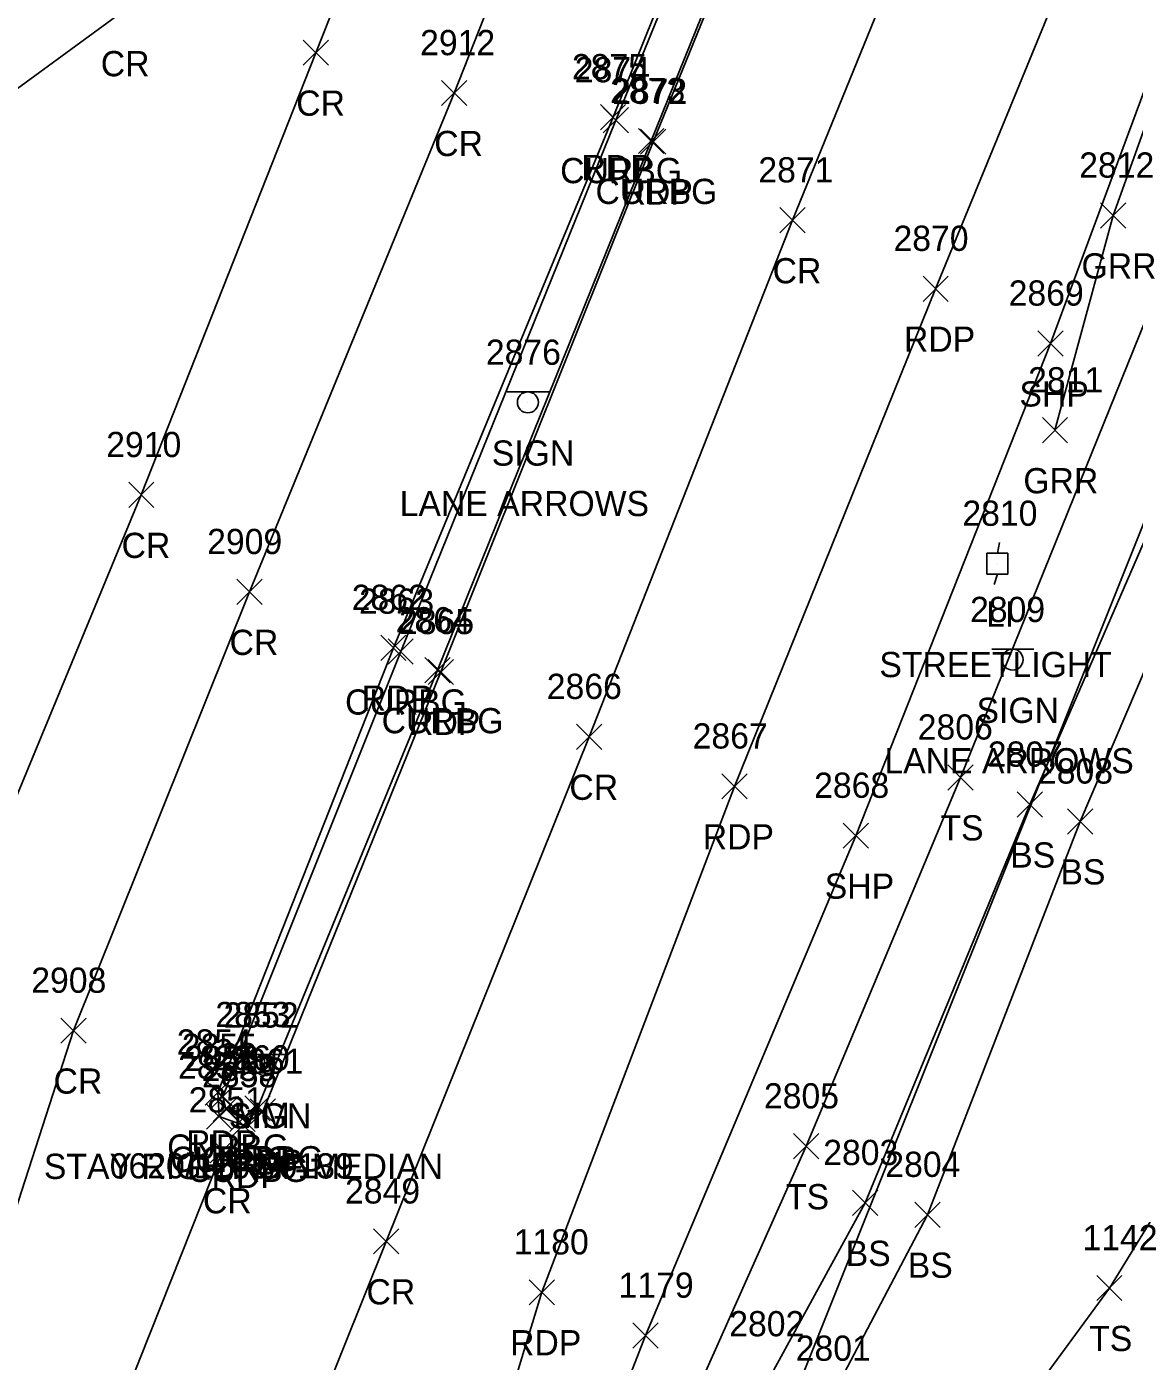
# Model space of a CAD drawing. Extents: x 1623612 to 1625808, y 621345 to 627748.
# Drawn here: x 1624751.6 to 1624839.4, y 626381.4 to 626487.2 of the extents above; entities that cross this region are included whole.
import ezdxf

# ---------------------------------------------------------------- set-up
doc = ezdxf.new("R2010")
doc.units = 0
for name, color, linetype in [('DCP', 7, 'Continuous'), ('L_A', 7, 'Continuous'), ('L_I', 7, 'Continuous'), ('L_TIC', 7, 'Continuous'), ('LELB', 7, 'Continuous'), ('P_A', 7, 'Continuous'), ('P_I', 7, 'Continuous'), ('P_TIC', 7, 'Continuous'), ('PET', 7, 'Continuous'), ('PRC', 7, 'Continuous'), ('PSP', 7, 'Continuous'), ('R_A', 7, 'Continuous'), ('R_I', 7, 'Continuous'), ('R_TIC', 7, 'Continuous'), ('RC', 7, 'Continuous'), ('RGR', 7, 'Continuous'), ('S_A', 7, 'Continuous'), ('S_C', 7, 'Continuous'), ('S_I', 7, 'Continuous'), ('SRM', 7, 'Continuous'), ('SSGN', 7, 'Continuous'), ('U_A', 7, 'Continuous'), ('U_C', 7, 'Continuous'), ('U_I', 7, 'Continuous'), ('ULP', 7, 'Continuous')]:
    doc.layers.add(name, color=color, linetype=linetype)

msp = doc.modelspace()

# ---------------------------------------------------------------- linework, layer by layer
at = {"layer": 'DCP'}
msp.add_lwpolyline([(1624809.95, 626372.49), (1624894.12, 626582.82)], dxfattribs=at)
at = {"layer": 'L_TIC'}
for points in [[(1624824.59, 626426.7), (1624826.59, 626428.7)], [(1624826.59, 626426.7), (1624824.59, 626428.7)], [(1624830.09, 626424.55), (1624832.09, 626426.55)], [(1624832.09, 626424.55), (1624830.09, 626426.55)], [(1624834.07, 626423.21), (1624836.07, 626425.21)], [(1624836.07, 626423.21), (1624834.07, 626425.21)], [(1624812.35, 626397.45), (1624814.35, 626399.45)], [(1624814.35, 626397.45), (1624812.35, 626399.45)], [(1624817.04, 626392.96), (1624819.04, 626394.96)], [(1624819.04, 626392.96), (1624817.04, 626394.96)], [(1624821.97, 626392.02), (1624823.97, 626394.02)], [(1624823.97, 626392.02), (1624821.97, 626394.02)], [(1624836.39, 626386.21), (1624838.39, 626388.21)], [(1624838.39, 626386.21), (1624836.39, 626388.21)]]:
    msp.add_lwpolyline(points, dxfattribs=at)
at = {"layer": 'LELB'}
for points in [[(1624803, 626375.22), (1624813.35, 626398.45), (1624825.59, 626427.7), (1624842.6, 626469.77), (1624853.82, 626508.25), (1624866.96, 626541.11), (1624879.6, 626570.92), (1624891.67, 626600.55), (1624909.69, 626627.37), (1624926.15, 626668.66), (1624945.08, 626696.18), (1624959.4, 626716.07), (1624979.06, 626741.61), (1624996.92, 626763.33), (1625023.93, 626790.77), (1625051.04, 626817.18), (1625076.24, 626838.55), (1625119.15, 626870.61), (1625147.29, 626888.18), (1625173.2, 626903.38), (1625206.27, 626920.6), (1625246.39, 626940.92)], [(1624810.6, 626380.38), (1624818.04, 626393.96), (1624831.09, 626425.55), (1624850.8, 626470.91), (1624859.76, 626506.71), (1624871.37, 626535.84), (1624886.95, 626567.84), (1624894.07, 626585.15), (1624895.49, 626590.47), (1624915.6, 626622.48), (1624934.63, 626664.39), (1624951.07, 626691.63), (1624965.13, 626713.06), (1624983.66, 626737.48), (1625004.4, 626758.94), (1625029.36, 626786.77), (1625054.16, 626807.16), (1625052.62, 626815.07), (1625083.54, 626836.73), (1625122.13, 626865.73), (1625150.08, 626884.49), (1625175.36, 626899.84), (1625209.28, 626915.51), (1625248.24, 626935.95)], [(1624815.3, 626378.44), (1624822.97, 626393.02), (1624835.07, 626424.21), (1624854.93, 626470.78), (1624864.02, 626503.22), (1624876, 626534.5), (1624889.39, 626566.85), (1624897.36, 626584.29), (1624900.1, 626587.8), (1624917.68, 626620.81), (1624936.92, 626663.47), (1624953.32, 626690.33), (1624968.57, 626711.23), (1624977.21, 626720.96), (1624986.38, 626735.04), (1625009.06, 626756.63), (1625033.16, 626784.59), (1625055.85, 626805.24), (1625057.84, 626806.47), (1625088.69, 626829.26), (1625128.34, 626855.41), (1625156.9, 626876.93)], [(1624911.43, 626189.27), (1624902.06, 626212.81), (1624885.19, 626234.26), (1624858.97, 626273.95), (1624836.34, 626299.76), (1624822.3, 626315.86), (1624819.42, 626329.22), (1624818.84, 626346.9), (1624823.2, 626367.84), (1624837.39, 626387.21), (1624868.75, 626438.34), (1624881.95, 626485.16), (1624894.55, 626521.87)]]:
    msp.add_lwpolyline(points, dxfattribs=at)
at = {"layer": 'P_TIC'}
for points in [[(1624773.5, 626484.17), (1624775.5, 626486.17)], [(1624775.5, 626484.17), (1624773.5, 626486.17)], [(1624784.45, 626480.97), (1624786.45, 626482.97)], [(1624786.45, 626480.97), (1624784.45, 626482.97)], [(1624797.05, 626479.06), (1624799.05, 626481.06)], [(1624799.05, 626479.06), (1624797.05, 626481.06)], [(1624800.24, 626477.11), (1624802.24, 626479.11)], [(1624802.24, 626477.11), (1624800.24, 626479.11)], [(1624811.27, 626470.88), (1624813.27, 626472.88)], [(1624813.27, 626470.88), (1624811.27, 626472.88)], [(1624822.62, 626465.45), (1624824.62, 626467.45)], [(1624824.62, 626465.45), (1624822.62, 626467.45)], [(1624831.73, 626461.11), (1624833.73, 626463.11)], [(1624833.73, 626461.11), (1624831.73, 626463.11)], [(1624759.66, 626449.1), (1624761.66, 626451.1)], [(1624761.66, 626449.1), (1624759.66, 626451.1)], [(1624768.23, 626441.41), (1624770.23, 626443.41)], [(1624770.23, 626441.41), (1624768.23, 626443.41)], [(1624779.64, 626436.98), (1624781.64, 626438.98)], [(1624781.64, 626436.98), (1624779.64, 626438.98)], [(1624783.4, 626435.06), (1624785.4, 626437.06)], [(1624785.4, 626435.06), (1624783.4, 626437.06)], [(1624795.16, 626429.92), (1624797.16, 626431.92)], [(1624797.16, 626429.92), (1624795.16, 626431.92)], [(1624806.67, 626425.99), (1624808.67, 626427.99)], [(1624808.67, 626425.99), (1624806.67, 626427.99)], [(1624816.3, 626422.08), (1624818.3, 626424.08)], [(1624818.3, 626422.08), (1624816.3, 626424.08)], [(1624754.28, 626406.62), (1624756.28, 626408.62)], [(1624756.28, 626406.62), (1624754.28, 626408.62)], [(1624765.73, 626401.72), (1624767.73, 626403.72)], [(1624767.73, 626401.72), (1624765.73, 626403.72)], [(1624765.73, 626401.72), (1624767.73, 626403.72)], [(1624767.73, 626401.72), (1624765.73, 626403.72)], [(1624765.83, 626399.8), (1624767.83, 626401.8)], [(1624767.83, 626399.8), (1624765.83, 626401.8)], [(1624769.3, 626400.2), (1624771.3, 626402.2)], [(1624771.3, 626400.2), (1624769.3, 626402.2)], [(1624767.74, 626399.13), (1624769.74, 626401.13)], [(1624769.74, 626399.13), (1624767.74, 626401.13)], [(1624766.12, 626397.13), (1624768.12, 626399.13)], [(1624768.12, 626397.13), (1624766.12, 626399.13)], [(1624779.07, 626389.91), (1624781.07, 626391.91)], [(1624781.07, 626389.91), (1624779.07, 626391.91)], [(1624791.4, 626385.87), (1624793.4, 626387.87)], [(1624793.4, 626385.87), (1624791.4, 626387.87)], [(1624799.63, 626382.44), (1624801.63, 626384.44)], [(1624801.63, 626382.44), (1624799.63, 626384.44)]]:
    msp.add_lwpolyline(points, dxfattribs=at)
at = {"layer": 'PET'}
for points in [[(1624766.73, 626402.72), (1624780.64, 626437.98), (1624798.05, 626480.06), (1624815.81, 626524.2), (1624827.52, 626552.84), (1624846.03, 626598.35), (1624859.48, 626631.2), (1624866.7, 626649.12), (1624872.17, 626667.17), (1624878.33, 626693.72), (1624888.34, 626729.13), (1624901.95, 626767.65), (1624921.26, 626815.38), (1624932.49, 626843.12), (1624948.41, 626882.32), (1624965.05, 626923.7), (1624979.42, 626958.68), (1624996.36, 626998.74), (1625014.07, 627035.12), (1625037.87, 627077.32), (1625060.67, 627111.97), (1625086.82, 627148.78)], [(1624766.73, 626402.72), (1624766.83, 626400.8), (1624768.74, 626400.13), (1624770.3, 626401.2), (1624784.4, 626436.06), (1624801.24, 626478.11), (1624819.49, 626522.96), (1624830.85, 626551.33), (1624849.51, 626596.84), (1624862.82, 626629.63), (1624870.03, 626647.48), (1624887.2, 626689.75), (1624900.85, 626722.92), (1624916.26, 626761.13), (1624935.59, 626808.93), (1624946.63, 626835.79), (1624962.93, 626876.24), (1624979.58, 626917.12), (1624994.1, 626953.25), (1625010.3, 626991.9), (1625027.96, 627028.75), (1625048.74, 627069.01), (1625070.59, 627104.96), (1625095.62, 627141.4)], [(1624787.66, 626371.25), (1624792.4, 626386.87), (1624807.67, 626426.99), (1624823.62, 626466.45), (1624842.65, 626512.83), (1624858.28, 626551.42), (1624873.9, 626593.46)]]:
    msp.add_lwpolyline(points, dxfattribs=at)
at = {"layer": 'PRC'}
for points in [[(1624734.72, 626386.78), (1624744.9, 626412.05), (1624760.66, 626450.1), (1624774.5, 626485.17), (1624790.6, 626525.88), (1624807.67, 626567), (1624823.36, 626605.3), (1624843.35, 626654.29), (1624857.69, 626692.78)], [(1624746.25, 626379.72), (1624755.28, 626407.62), (1624769.23, 626442.41), (1624785.45, 626481.97), (1624800.21, 626519.37), (1624817.93, 626562.99), (1624833.55, 626600.88), (1624853.94, 626650.59), (1624866.71, 626682.78)], [(1624769.71, 626365.07), (1624780.07, 626390.91), (1624796.16, 626430.92), (1624812.27, 626471.88), (1624830.75, 626517.25), (1624847.51, 626558.11), (1624861.26, 626592.1)], [(1624657.54, 626467.38), (1624680.7, 626465.41), (1624702.49, 626466.85), (1624727.83, 626471.96), (1624748.65, 626480.73), (1624759.02, 626488.3)], [(1624754.79, 626367.08), (1624767.12, 626398.13)]]:
    msp.add_lwpolyline(points, dxfattribs=at)
at = {"layer": 'PSP'}
msp.add_lwpolyline([(1624794.65, 626368.04), (1624800.63, 626383.44), (1624817.3, 626423.08), (1624832.73, 626462.11), (1624850.47, 626510.04), (1624865.43, 626546.52), (1624882.91, 626590.11), (1624893.72, 626613.2), (1624905.71, 626637.22), (1624924.51, 626670), (1624942.43, 626698.12), (1624956.64, 626717.85), (1624976.67, 626743.84), (1624995.18, 626765.37), (1625020.7, 626793.24), (1625048.65, 626820.06), (1625074.48, 626841.9), (1625117.11, 626873.56), (1625144.96, 626891.32), (1625172.26, 626906.31), (1625205.02, 626923.68), (1625245.42, 626943.67)], dxfattribs=at)
at = {"layer": 'R_TIC'}
for points in [[(1624797.28, 626478.82), (1624799.28, 626480.82)], [(1624799.28, 626478.82), (1624797.28, 626480.82)], [(1624800.08, 626477.17), (1624802.08, 626479.17)], [(1624802.08, 626477.17), (1624800.08, 626479.17)], [(1624836.69, 626471.26), (1624838.69, 626473.26)], [(1624838.69, 626471.26), (1624836.69, 626473.26)], [(1624832.08, 626454.23), (1624834.08, 626456.23)], [(1624834.08, 626454.23), (1624832.08, 626456.23)], [(1624780.22, 626436.68), (1624782.22, 626438.68)], [(1624782.22, 626436.68), (1624780.22, 626438.68)], [(1624783.13, 626435.2), (1624785.13, 626437.2)], [(1624785.13, 626435.2), (1624783.13, 626437.2)], [(1624766.13, 626401.39), (1624768.13, 626403.39)], [(1624768.13, 626401.39), (1624766.13, 626403.39)], [(1624766.13, 626401.39), (1624768.13, 626403.39)], [(1624768.13, 626401.39), (1624766.13, 626403.39)], [(1624766.37, 626400.42), (1624768.37, 626402.42)], [(1624768.37, 626400.42), (1624766.37, 626402.42)], [(1624768.87, 626400.46), (1624770.87, 626402.46)], [(1624770.87, 626400.46), (1624768.87, 626402.46)], [(1624767.69, 626399.62), (1624769.69, 626401.62)], [(1624769.69, 626399.62), (1624767.69, 626401.62)]]:
    msp.add_lwpolyline(points, dxfattribs=at)
at = {"layer": 'RC'}
for points in [[(1624767.13, 626402.39), (1624781.22, 626437.68), (1624798.28, 626479.82), (1624816.29, 626523.98), (1624827.95, 626552.72), (1624846.41, 626598.09), (1624859.85, 626631.15), (1624867.05, 626649.04), (1624872.5, 626667.1), (1624878.6, 626693.46), (1624888.65, 626729.07), (1624902.23, 626767.49), (1624921.49, 626815.28), (1624932.62, 626843.03), (1624948.65, 626882.09), (1624965.45, 626923.58), (1624979.81, 626958.53), (1624996.62, 626998.96), (1625014.22, 627035.04), (1625038.15, 627077.1), (1625060.78, 627111.92), (1625087.16, 627148.54)], [(1624767.13, 626402.39), (1624767.37, 626401.42), (1624768.69, 626400.62), (1624769.87, 626401.46), (1624784.13, 626436.2), (1624801.08, 626478.17), (1624819.28, 626523.2), (1624830.67, 626551.37), (1624849.2, 626596.97), (1624862.54, 626629.65), (1624869.78, 626647.63), (1624886.89, 626689.79), (1624900.54, 626723.06), (1624916.05, 626761.33), (1624935.24, 626808.75), (1624946.34, 626835.89), (1624962.53, 626876.37), (1624979.31, 626917.29), (1624993.83, 626953.39), (1625009.94, 626991.92), (1625027.68, 627028.97), (1625048.28, 627069.21), (1625070.34, 627105.18), (1625095.35, 627141.59)]]:
    msp.add_lwpolyline(points, dxfattribs=at)
at = {"layer": 'RGR'}
msp.add_lwpolyline([(1624833.08, 626455.23), (1624837.69, 626472.26), (1624850.98, 626509.38), (1624864.06, 626541.69), (1624877.05, 626573.21), (1624889.19, 626602.45), (1624903.3, 626631.29)], dxfattribs=at)
at = {"layer": 'SRM'}
msp.add_lwpolyline([(1624769.17, 626405.52), (1624770.42, 626405.52), (1624770.42, 626404.27), (1624769.17, 626404.27)], close=True, dxfattribs=at)
msp.add_circle((1624769.79, 626404.9), 0.0833, dxfattribs=at)
at = {"layer": 'SSGN'}
for p, q in [((1624789.65, 626458.28), (1624792.99, 626458.28)), ((1624791.3, 626457.44), (1624791.3, 626457.44)), ((1624828.07, 626437.87), (1624831.41, 626437.87)), ((1624829.72, 626437.04), (1624829.72, 626437.04)), ((1624768.82, 626405.72), (1624772.15, 626405.72)), ((1624770.46, 626404.88), (1624770.46, 626404.88))]:
    msp.add_line(p, q, dxfattribs=at)
for centre in [(1624791.3, 626457.44), (1624829.72, 626437.04), (1624770.46, 626404.88)]:
    msp.add_circle(centre, 0.833, dxfattribs=at)
at = {"layer": 'ULP'}
for p, q in [((1624828.69, 626446.32), (1624828.52, 626445.49)), ((1624827.69, 626443.82), (1624827.69, 626445.49)), ((1624827.69, 626445.49), (1624829.35, 626445.49)), ((1624828.52, 626444.65), (1624828.52, 626444.65)), ((1624829.35, 626445.49), (1624829.35, 626443.82)), ((1624829.35, 626443.82), (1624827.69, 626443.82)), ((1624828.27, 626442.99), (1624828.52, 626443.82))]:
    msp.add_line(p, q, dxfattribs=at)

# ---------------------------------------------------------------- texts
at = {"layer": 'L_A'}
for s, p in [('TS', (1624824, 626422.7)), ('BS', (1624829.53, 626420.55)), ('BS', (1624833.51, 626419.21)), ('TS', (1624811.76, 626393.45)), ('BS', (1624816.49, 626388.96)), ('BS', (1624821.41, 626388.02)), ('TS', (1624835.79, 626382.21))]:
    msp.add_text(s, height=2, dxfattribs=at).set_placement(p)
at = {"layer": 'L_I'}
for s, p in [('2806', (1624822.2, 626430.7)), ('2807', (1624827.75, 626428.55)), ('2808', (1624831.73, 626427.21)), ('2805', (1624810.01, 626401.45)), ('2803', (1624814.71, 626396.96)), ('2804', (1624819.63, 626396.02)), ('1142', (1624835.26, 626390.21)), ('2802', (1624807.26, 626383.38)), ('2801', (1624812.53, 626381.44))]:
    msp.add_text(s, height=2, dxfattribs=at).set_placement(p)
at = {"layer": 'P_A'}
for s, p in [('CR', (1624757.45, 626483.3)), ('CR', (1624772.94, 626480.17)), ('CR', (1624783.88, 626476.97)), ('RDP', (1624795.54, 626475.06)), ('RDP', (1624798.73, 626473.11)), ('CR', (1624810.7, 626466.88)), ('RDP', (1624821.11, 626461.45)), ('SHP', (1624830.26, 626457.11)), ('CR', (1624759.1, 626445.1)), ('CR', (1624767.66, 626437.41)), ('RDP', (1624778.13, 626432.98)), ('RDP', (1624781.89, 626431.06)), ('CR', (1624794.59, 626425.92)), ('RDP', (1624805.16, 626421.99)), ('SHP', (1624814.83, 626418.08)), ('CR', (1624753.71, 626402.62)), ('RDP', (1624764.22, 626397.72)), ('RDP', (1624764.22, 626397.72)), ('RDP', (1624767.79, 626396.2)), ('RDP', (1624764.31, 626395.8)), ('RDP', (1624766.23, 626395.13)), ('CR', (1624765.55, 626393.13)), ('CR', (1624778.51, 626385.91)), ('RDP', (1624789.89, 626381.87))]:
    msp.add_text(s, height=2, dxfattribs=at).set_placement(p)
at = {"layer": 'P_I'}
for s, p in [('2912', (1624782.76, 626484.97)), ('2875', (1624794.79, 626483.06)), ('2872', (1624797.98, 626481.11)), ('2871', (1624809.57, 626474.88)), ('2870', (1624820.28, 626469.45)), ('2869', (1624829.41, 626465.11)), ('2910', (1624757.88, 626453.1)), ('2909', (1624765.88, 626445.41)), ('2862', (1624777.34, 626440.98)), ('2865', (1624781.09, 626439.06)), ('2866', (1624792.8, 626433.92)), ('2867', (1624804.36, 626429.99)), ('2868', (1624813.99, 626426.08)), ('2908', (1624751.94, 626410.62)), ('2854', (1624763.47, 626405.72)), ('2854', (1624763.47, 626405.72)), ('2857', (1624763.57, 626403.8)), ('2861', (1624767.56, 626404.2)), ('2858', (1624765.48, 626403.13)), ('2851', (1624764.42, 626401.13)), ('2849', (1624776.81, 626393.91)), ('1180', (1624790.18, 626389.87)), ('1179', (1624798.49, 626386.44))]:
    msp.add_text(s, height=2, dxfattribs=at).set_placement(p)
at = {"layer": 'R_A'}
for s, p in [('CURBG', (1624793.86, 626474.82)), ('CURBG', (1624796.66, 626473.17)), ('GRR', (1624835.18, 626467.26)), ('GRR', (1624830.57, 626450.23)), ('CURBG', (1624776.81, 626432.68)), ('CURBG', (1624779.71, 626431.2)), ('CURBG', (1624762.71, 626397.39)), ('CURBG', (1624762.71, 626397.39)), ('CURBG', (1624762.95, 626396.42)), ('CURBG', (1624765.45, 626396.46)), ('CURBG', (1624764.28, 626395.62))]:
    msp.add_text(s, height=2, dxfattribs=at).set_placement(p)
at = {"layer": 'R_I'}
for s, p in [('2874', (1624795.02, 626482.82)), ('2873', (1624797.82, 626481.17)), ('2812', (1624835, 626475.26)), ('2811', (1624830.95, 626458.23)), ('2863', (1624777.92, 626440.68)), ('2864', (1624780.82, 626439.2)), ('2855', (1624763.87, 626405.39)), ('2855', (1624763.87, 626405.39)), ('2860', (1624766.47, 626404.46)), ('2856', (1624764.06, 626404.42)), ('2859', (1624765.43, 626403.62))]:
    msp.add_text(s, height=2, dxfattribs=at).set_placement(p)
at = {"layer": 'S_A'}
for s, p in [('SIGN', (1624788.44, 626452.42)), ('SIGN', (1624826.86, 626432.02)), ('SIGN', (1624767.6, 626399.86)), ('MM', (1624767.98, 626399.9))]:
    msp.add_text(s, height=2, dxfattribs=at).set_placement(p)
at = {"layer": 'S_C'}
for s, p in [('LANE ARROWS', (1624781.14, 626448.42)), ('LANE ARROWS', (1624819.56, 626428.02)), ('STAY RIGHT OF MEDIAN', (1624752.94, 626395.86)), ('0620/1203/0139', (1624758.16, 626395.9))]:
    msp.add_text(s, height=2, dxfattribs=at).set_placement(p)
at = {"layer": 'S_I'}
for s, p in [('2876', (1624787.97, 626460.42)), ('2809', (1624826.35, 626440.02)), ('2853', (1624766.53, 626407.9)), ('2852', (1624767.18, 626407.86))]:
    msp.add_text(s, height=2, dxfattribs=at).set_placement(p)
at = {"layer": 'U_A'}
msp.add_text('LI', height=2, dxfattribs=at).set_placement((1624827.62, 626439.65))
at = {"layer": 'U_C'}
msp.add_text('STREETLIGHT', height=2, dxfattribs=at).set_placement((1624819.16, 626435.65))
at = {"layer": 'U_I'}
msp.add_text('2810', height=2, dxfattribs=at).set_placement((1624825.74, 626447.65))

doc.saveas('drawing.dxf')
